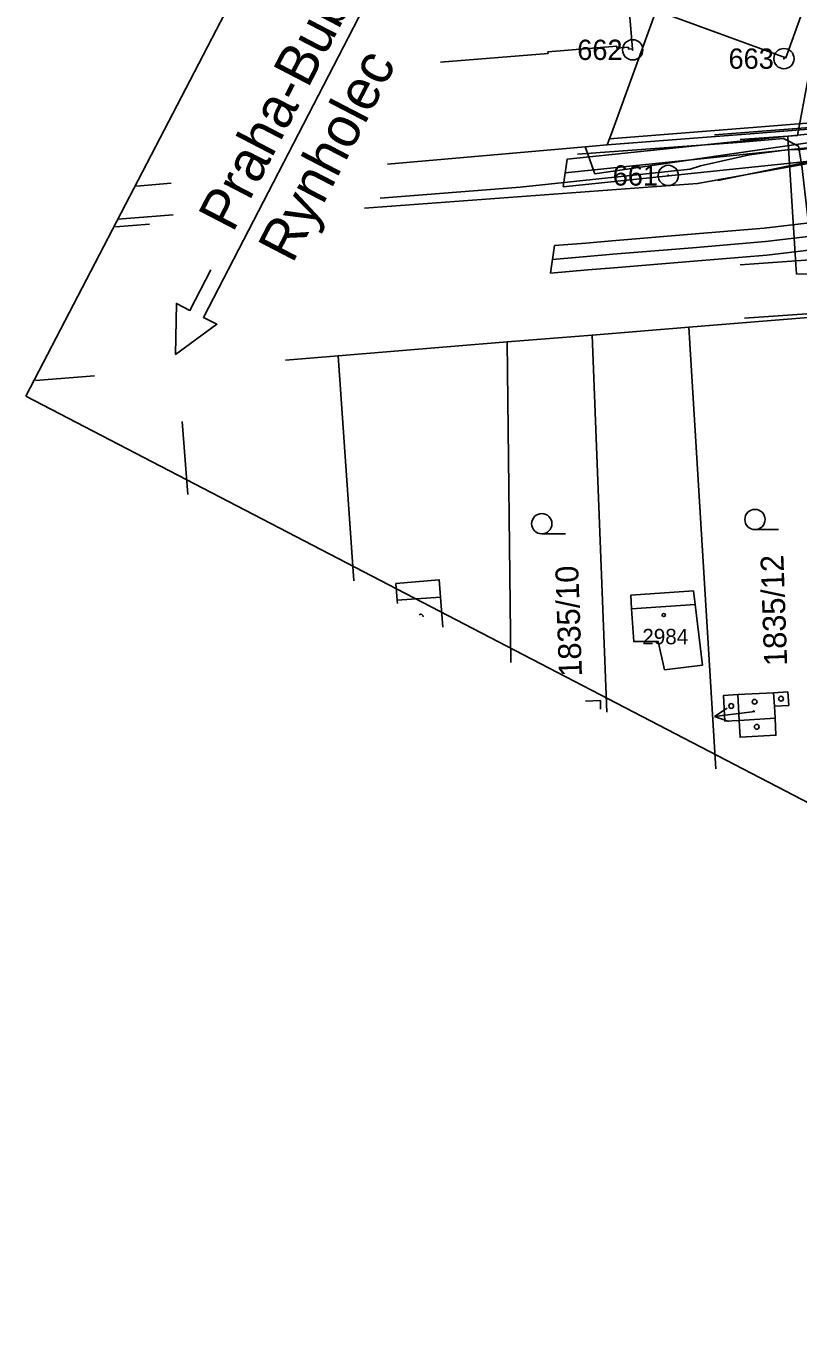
# Model space of a CAD drawing. Extents: x -781083 to -763634, y -1029516 to -1022695.
# Drawn here: x -765336.1 to -765279.1, y -1024432.1 to -1024336.1 of the extents above; entities that cross this region are included whole.
import ezdxf

# ---------------------------------------------------------------- set-up
doc = ezdxf.new("R2010")
doc.units = 0
for name, color, linetype in [('CETIN_nezaměřený', 7, 'Continuous'), ('CETIN_zaměřený', 7, 'Continuous'), ('GasNet_ochr. pásmo', 7, 'Continuous'), ('GasNet_plyn NTL', 7, 'Continuous'), ('GasNet_plyn STL', 7, 'Continuous'), ('Hranice parcel', 7, 'Continuous'), ('Parcelní čísla', 7, 'Continuous'), ('Pop  PČ popisy', 7, 'Continuous'), ('směry', 7, 'Continuous'), ('Vnitřní kresba', 7, 'Continuous'), ('Vrstva 17', 7, 'Continuous'), ('Vrstva 49', 7, 'Continuous'), ('Vrstva 51', 7, 'Continuous'), ('Značky bodu BP', 7, 'Continuous'), ('Značky budov', 7, 'Continuous'), ('Značky kultur', 7, 'Continuous'), ('ČEZd_VN_podzemní', 7, 'Continuous')]:
    doc.layers.add(name, color=color, linetype=linetype)

# ---------------------------------------------------------------- blocks, each defined once
blk = doc.blocks.new('4.02_1')
at = {"layer": 'Značky budov'}
blk.add_circle((-0.05, 0.01), 1.17, dxfattribs=at)
blk = doc.blocks.new('4.02')
at = {"layer": 'Značky budov'}
blk.add_circle((-0.07, 0.01), 1.75, dxfattribs=at)
blk = doc.blocks.new('3.04')
at = {"layer": 'Značky kultur'}
blk.add_line((0.07, 0), (17.57, 0), dxfattribs=at)
blk.add_circle((0.07, 7.5), 7.5, dxfattribs=at)
blk = doc.blocks.new('1.01')
at = {"layer": 'Značky bodu BP'}
for radius in [7.5, 0.3]:
    blk.add_circle((0, 0), radius, dxfattribs=at)

msp = doc.modelspace()

# ---------------------------------------------------------------- linework, layer by layer
msp.add_lwpolyline([(-765336.117, -1024363.479), (-765204.05, -1024432.093), (-764769.725, -1023596.107), (-764901.792, -1023527.494)], close=True)
at = {"layer": 'CETIN_nezaměřený'}
for points in [[(-765279.8, -1024344.26), (-765279.1, -1024344.21), (-765278.17, -1024339.31), (-765274.62, -1024329.4), (-765276.22, -1024328.8)], [(-765279.8, -1024344.26), (-765283.32, -1024344.5)], [(-765233.96, -1024367.52), (-765248.86, -1024367.26), (-765249.36, -1024367.26), (-765249.41, -1024354.76), (-765253.61, -1024354.77), (-765279.17, -1024354.44), (-765279.21, -1024353.74), (-765279.77, -1024344.76), (-765279.8, -1024344.26)]]:
    msp.add_lwpolyline(points, dxfattribs=at)
at = {"layer": 'CETIN_zaměřený'}
msp.add_lwpolyline([(-765276.8, -1024353.99), (-765277.62, -1024353.75), (-765278.03, -1024352.84), (-765278.76, -1024346.44), (-765279.01, -1024345), (-765280.13, -1024344.42), (-765283.21, -1024344.71), (-765295.35, -1024345.6)], dxfattribs=at)
at = {"layer": 'GasNet_ochr. pásmo'}
for points in [[(-765271.586, -1024345.427), (-765296.406, -1024347.993), (-765296.108, -1024345.951), (-765271.754, -1024343.433)], [(-765264.828, -1024351.092), (-765281.35, -1024353.045), (-765286.764, -1024353.496), (-765292.658, -1024353.986), (-765294.578, -1024354.146), (-765297.336, -1024354.375), (-765297.04, -1024352.343), (-765294.744, -1024352.152), (-765292.824, -1024351.992), (-765286.93, -1024351.502), (-765281.55, -1024351.055), (-765264.412, -1024349.028)]]:
    msp.add_lwpolyline(points, dxfattribs=at)
at = {"layer": 'GasNet_plyn NTL'}
msp.add_lwpolyline([(-765185.486, -1024348.463), (-765200.18, -1024349.25), (-765208.725, -1024350.098), (-765209.45, -1024350.17), (-765218.22, -1024350.7), (-765219.37, -1024350.81), (-765220.35, -1024350.79), (-765228.58, -1024358.71), (-765231.8, -1024361.32), (-765237.17, -1024360.43), (-765240.46, -1024359.701), (-765251.53, -1024355.44), (-765252.3, -1024355.07), (-765252.33, -1024354.89), (-765255.22, -1024351.44), (-765256.22, -1024351.45), (-765260.74, -1024351.49), (-765266.9, -1024352.06), (-765267.16, -1024348.53), (-765267.74, -1024344.17), (-765271.67, -1024344.43), (-765296.257, -1024346.972)], dxfattribs=at)
at = {"layer": 'GasNet_plyn STL'}
msp.add_lwpolyline([(-765189.386, -1024346.571), (-765208.21, -1024348.24), (-765207.92, -1024349.91), (-765207.65, -1024363.32), (-765214.51, -1024363.44), (-765218.95, -1024364.16), (-765223.71, -1024363.84), (-765230.731, -1024362.612), (-765232.021, -1024362.359), (-765246.402, -1024359.535), (-765246.442, -1024359.527), (-765247.437, -1024359.332), (-765255.625, -1024356.797), (-765257.52, -1024356.21), (-765261.55, -1024351.8), (-765264.62, -1024350.06), (-765281.45, -1024352.05), (-765286.847, -1024352.499), (-765292.741, -1024352.989), (-765294.661, -1024353.149), (-765297.188, -1024353.359)], dxfattribs=at)
at = {"layer": 'Hranice parcel'}
for p, q in [((-765294.78, -1024345.04), (-765293.16, -1024344.91)), ((-765287.12, -1024358.38), (-765277.4, -1024357.59)), ((-765300.55, -1024359.46), (-765294.27, -1024358.96)), ((-765294.27, -1024358.96), (-765287.12, -1024358.38)), ((-765293.181, -1024386.826), (-765294.27, -1024358.96)), ((-765285.122, -1024391.012), (-765287.12, -1024358.38)), ((-765313.03, -1024360.5), (-765300.55, -1024359.46)), ((-765300.282, -1024383.136), (-765300.55, -1024359.46)), ((-765316.922, -1024360.816), (-765313.03, -1024360.5)), ((-765311.881, -1024377.11), (-765313.03, -1024360.5)), ((-765335.408, -1024362.32), (-765331.045, -1024361.964)), ((-765324.151, -1024370.735), (-765324.564, -1024365.331))]:
    msp.add_line(p, q, dxfattribs=at)
for points in [[(-765289.53, -1024334.97), (-765279.95, -1024338.48), (-765276.17, -1024327.99), (-765285.72, -1024324.55)], [(-765257.43, -1024331.1), (-765260.44, -1024333.79), (-765266.45, -1024339.16), (-765270.92, -1024343.16), (-765281.95, -1024344.03), (-765293.16, -1024344.91)], [(-765288.26, -1024331.49), (-765291.77, -1024331.89), (-765291.28, -1024337.81), (-765291.58, -1024337.83), (-765291.59, -1024337.69), (-765292.44, -1024337.76), (-765292.45, -1024337.62), (-765297.54, -1024338.04), (-765297.53, -1024338.14), (-765305.484, -1024338.799)], [(-765293.16, -1024344.91), (-765292.99, -1024344.45), (-765292.75, -1024343.79), (-765289.53, -1024334.97)], [(-765271.62, -1024343.79), (-765273.41, -1024345.39), (-765286.47, -1024347.76), (-765311.089, -1024349.588)], [(-765294.78, -1024345.04), (-765294.06, -1024347.03), (-765282.42, -1024345.34), (-765276.81, -1024344.52), (-765271.62, -1024343.79)], [(-765309.392, -1024346.323), (-765294.78, -1024345.04)], [(-765327.943, -1024347.951), (-765325.396, -1024347.727)], [(-765326.975, -1024350.767), (-765329.504, -1024350.955)], [(-765305.297, -1024380.531), (-765305.47, -1024378.31), (-765305.57, -1024377.04), (-765308.77, -1024377.32), (-765308.68, -1024378.55), (-765308.663, -1024378.782)], [(-765288.91, -1024383.69), (-765286.12, -1024383.35), (-765286.66, -1024378.86), (-765291.35, -1024379.17), (-765291.19, -1024381.6), (-765289.39, -1024381.59), (-765288.91, -1024383.69)], [(-765293.64, -1024386.587), (-765293.65, -1024385.96), (-765294.768, -1024386.001)], [(-765280.8, -1024386.38), (-765279.74, -1024386.32), (-765279.8, -1024385.32), (-765280.86, -1024385.38), (-765283.5, -1024385.52), (-765284.55, -1024385.58), (-765284.45, -1024387.48), (-765283.4, -1024387.42), (-765283.33, -1024388.67), (-765280.68, -1024388.52), (-765280.75, -1024387.27), (-765280.8, -1024386.38)]]:
    msp.add_lwpolyline(points, dxfattribs=at)
at = {"layer": 'Pop  PČ popisy'}
for p, q in [((-765285.219, -1024387.126), (-765284.286, -1024386.507)), ((-765282.24, -1024386.76), (-765285.219, -1024387.126)), ((-765282.4, -1024386.72), (-765282.24, -1024386.76)), ((-765285.219, -1024387.126), (-765284.164, -1024387.501))]:
    msp.add_line(p, q, dxfattribs=at)
at = {"layer": 'směry'}
msp.add_lwpolyline([(-765309.326, -1024331.2), (-765323.007, -1024357.644), (-765322.009, -1024358.16), (-765325.054, -1024360.379), (-765325.002, -1024356.612), (-765324.004, -1024357.128), (-765322.456, -1024354.135)], dxfattribs=at)
at = {"layer": 'Vnitřní kresba'}
for p, q in [((-765271.11, -1024342.72), (-765281.78, -1024343.56)), ((-765281.78, -1024343.56), (-765292.99, -1024344.45)), ((-765305.47, -1024378.31), (-765308.68, -1024378.55)), ((-765286.78, -1024377.86), (-765291.41, -1024378.16)), ((-765291.35, -1024379.17), (-765291.41, -1024378.16)), ((-765286.66, -1024378.86), (-765286.78, -1024377.86)), ((-765283.5, -1024385.52), (-765283.4, -1024387.42)), ((-765280.8, -1024386.38), (-765280.86, -1024385.38)), ((-765283.4, -1024387.42), (-765280.75, -1024387.27))]:
    msp.add_line(p, q, dxfattribs=at)
at = {"layer": 'Vrstva 17'}
msp.add_lwpolyline([(-765266.345, -1024339.081), (-765270.846, -1024343.058), (-765285.218, -1024344.154)], dxfattribs=at)
at = {"layer": 'Vrstva 49'}
for points in [[(-765268.485, -1024352.701), (-765283.331, -1024353.769)], [(-765257.498, -1024356.169), (-765262.1, -1024356.254), (-765283.002, -1024357.714)]]:
    msp.add_lwpolyline(points, dxfattribs=at)
at = {"layer": 'Vrstva 51'}
for points in [[(-765284.979, -1024347.539), (-765270.723, -1024344.592), (-765270.846, -1024343.058)], [(-765283.331, -1024353.769), (-765268.485, -1024352.701), (-765249.895, -1024350.117), (-765245.658, -1024350.908)]]:
    msp.add_lwpolyline(points, dxfattribs=at)
at = {"layer": 'Značky budov'}
msp.add_arc((-765306.937, -1024379.759), 0.175, 356.57399, 128.51898, dxfattribs=at)
at = {"layer": 'ČEZd_VN_podzemní'}
for points in [[(-765168.19, -1024337.56), (-765172.24, -1024337.59), (-765176.18, -1024337.66), (-765184.15, -1024337.97), (-765188.11, -1024337.86), (-765195.45, -1024338.12), (-765203.31, -1024339.25), (-765206.92, -1024339.32), (-765223.26, -1024341.24), (-765223.54, -1024341.17), (-765227.7, -1024341.2), (-765232.88, -1024341.47), (-765244.45, -1024342.64), (-765253.33, -1024342.3), (-765262.78, -1024343.13), (-765268.54, -1024344.04), (-765275.43, -1024344.82), (-765279.03, -1024345.26), (-765279.68, -1024345.25), (-765282.64, -1024345.64), (-765286.26, -1024346.45), (-765287.02, -1024346.69), (-765299.59, -1024348.02), (-765309.939, -1024348.848)], [(-765325.238, -1024350.073), (-765329.322, -1024350.4)]]:
    msp.add_lwpolyline(points, dxfattribs=at)

# ---------------------------------------------------------------- block references
at = {"layer": 'Značky bodu BP', "xscale": 0.1, "yscale": 0.10000000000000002}
for p in [(-765291.27, -1024337.88), (-765280.09, -1024338.53), (-765288.64, -1024347.16)]:
    msp.add_blockref('1.01', p, dxfattribs=at)
at = {"layer": 'Značky budov', "xscale": 0.1, "yscale": 0.10000000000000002}
for name, p in [('4.02_1', (-765288.97, -1024379.64)), ('4.02', (-765282.25, -1024386.05)), ('4.02', (-765280.3, -1024385.82)), ('4.02', (-765283.98, -1024386.36)), ('4.02', (-765282.09, -1024387.9))]:
    msp.add_blockref(name, p, dxfattribs=at)
at = {"layer": 'Značky kultur', "xscale": 0.1, "yscale": 0.10000000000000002}
for p in [(-765298, -1024373.64), (-765282.24, -1024373.33)]:
    msp.add_blockref('3.04', p, dxfattribs=at)

# ---------------------------------------------------------------- texts
at = {"layer": 'Parcelní čísla'}
for s, p in [('1835/12', (-765279.847, -1024383.376)), ('1835/10', (-765295.015, -1024384.173))]:
    msp.add_text(s, height=1.7, rotation=92, dxfattribs=at).set_placement(p)
msp.add_text('2984', height=1.14, dxfattribs=at).set_placement((-765290.56, -1024381.8))
at = {"layer": 'směry'}
for s, p in [('Praha-Bubny', (-765320.826, -1024351.453)), ('Rynholec', (-765316.421, -1024353.735))]:
    msp.add_text(s, height=2.9952, rotation=62.55167, dxfattribs=at).set_placement(p)
at = {"layer": 'Značky bodu BP'}
for s, p in [('662', (-765295.368, -1024338.63)), ('663', (-765284.188, -1024339.28)), ('661', (-765292.745, -1024347.91))]:
    msp.add_text(s, height=1.5, dxfattribs=at).set_placement(p)

doc.saveas('drawing.dxf')
